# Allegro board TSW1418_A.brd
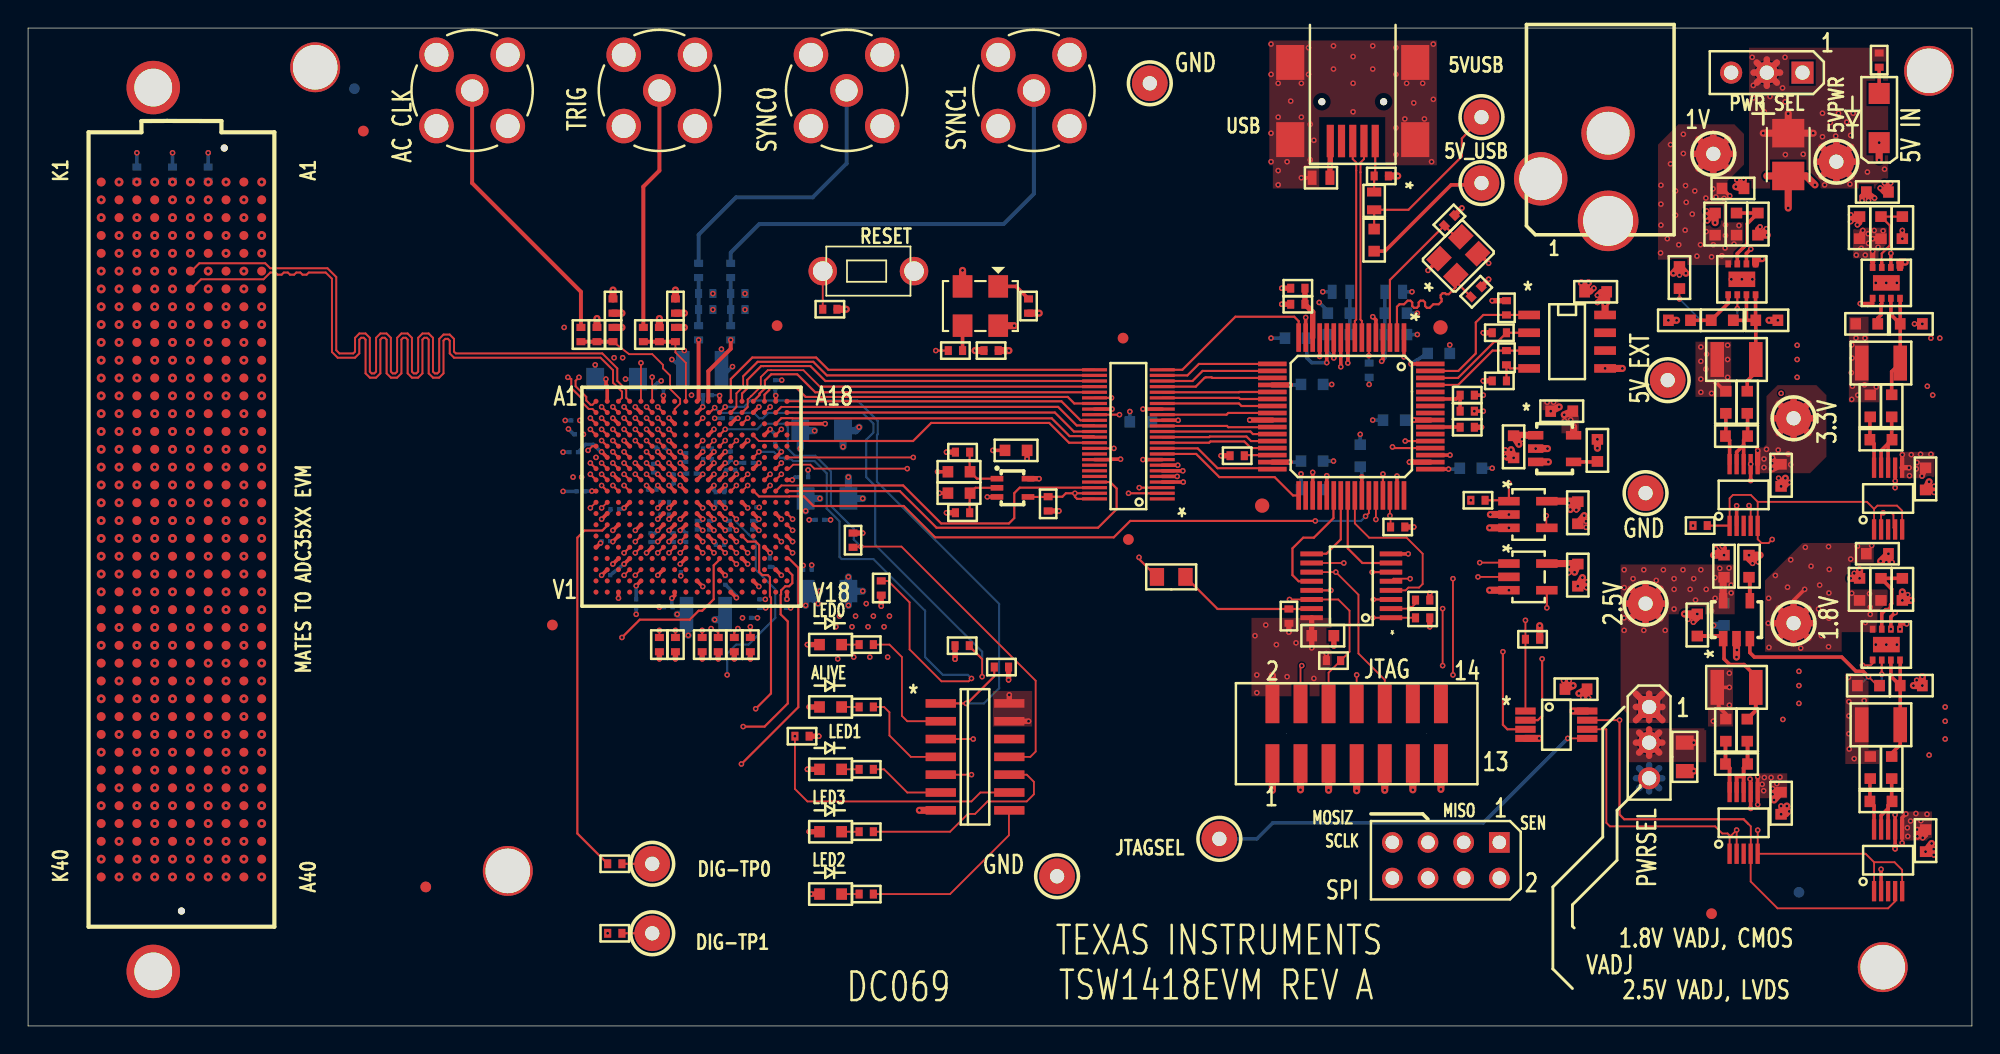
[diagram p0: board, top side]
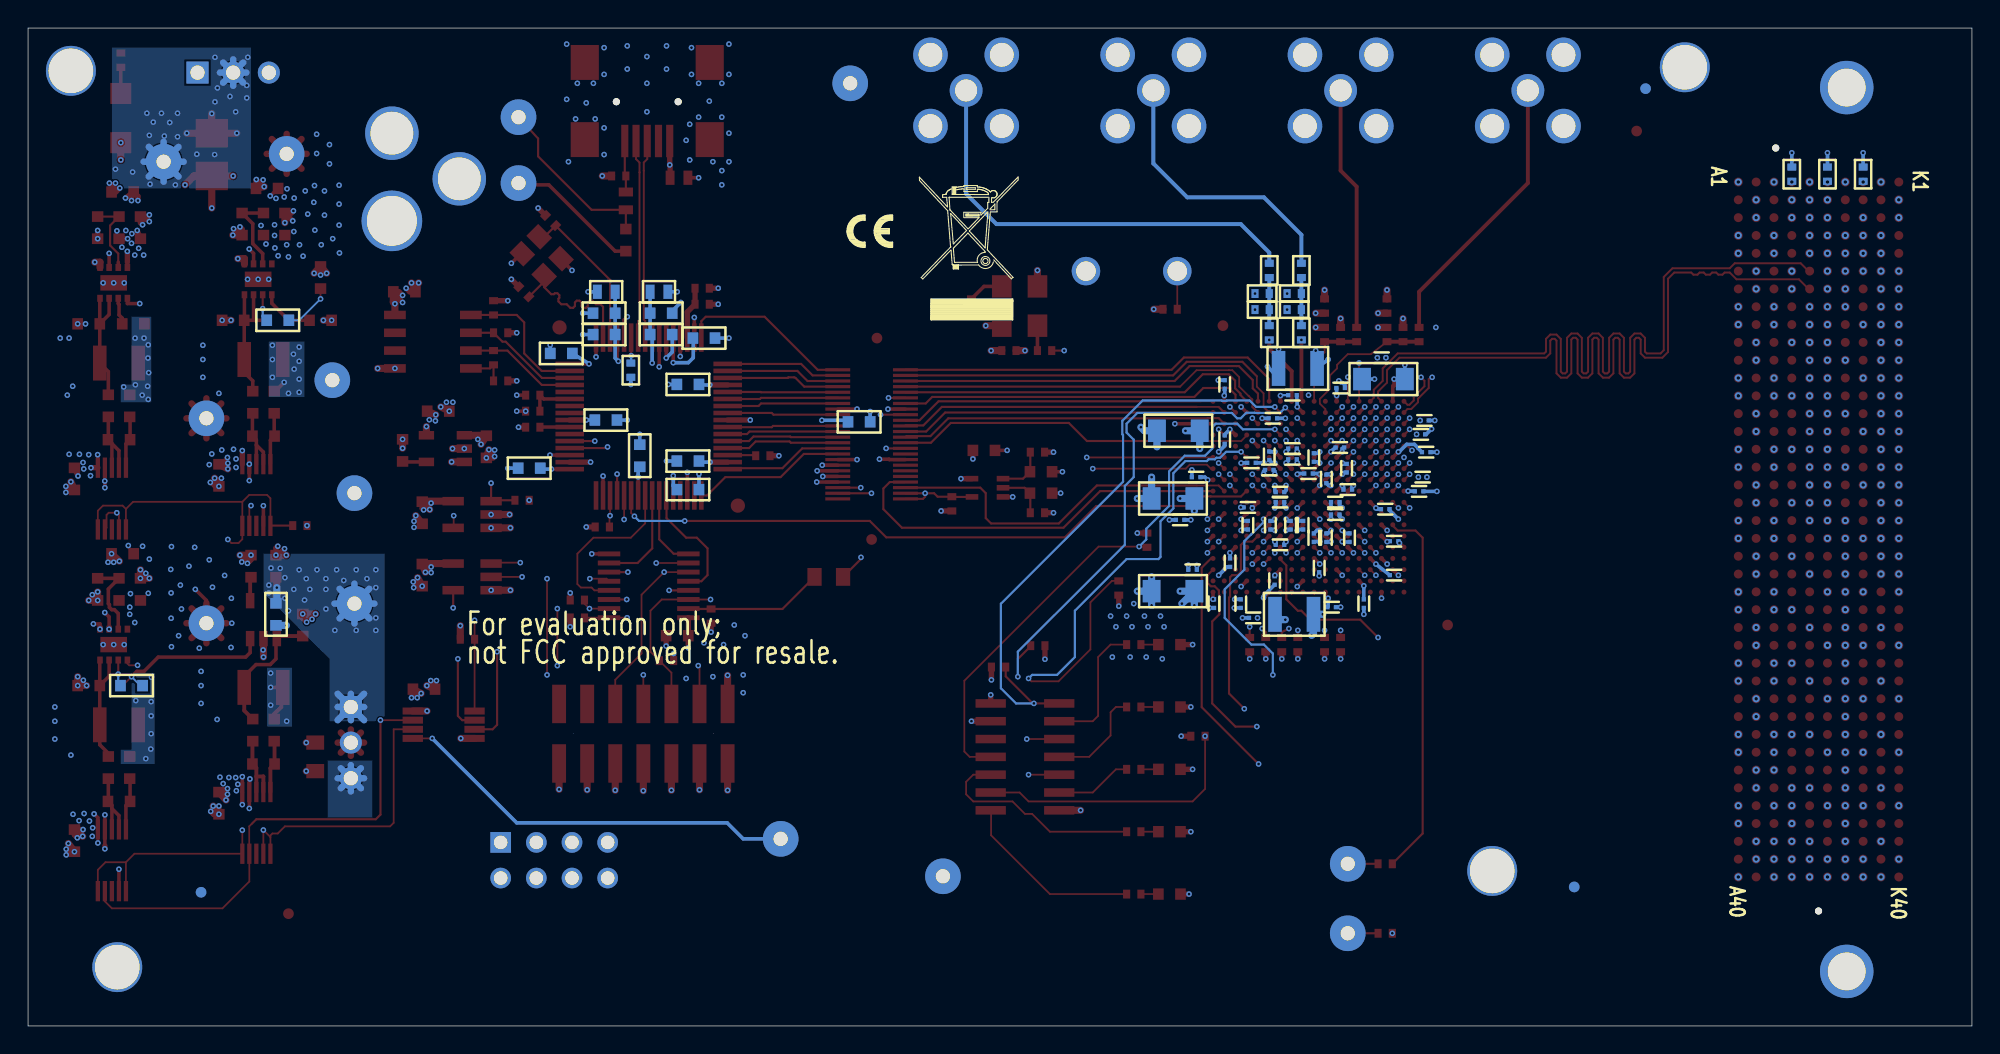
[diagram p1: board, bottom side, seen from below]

Outline 138.43 x 71.12 mm; copper layers: TOP, LY2-GND, LY3-SIGNAL, LY4-GND, LY5-SIGNAL, LY6-GND, LY7-PWR, LYR8-GND, LYR9-PWR, BOTTOM. Coordinates in mm from the lower left corner of the outline.
Outline path: 0,71.12 138.43,71.12 138.43,0 0,0 0,71.12

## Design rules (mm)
net group DCLK: nets DCLK_N DCLK_P
net group DCLKIN_FPGA: nets DCLKIN_FPGA_N DCLKIN_FPGA_P
net group DMP: nets DM DP
net group FCLK: nets FCLK_N FCLK_P
net group FPGA_CLK: nets FPGA_CLK_N FPGA_CLK_P
net group FPGA_REFCLK: nets FPGA_REFCLK_N FPGA_REFCLK_P
net group HA02: nets HA02_N HA02_P
net group HA03: nets HA03_N HA03_P
net group HA04: nets HA04_N HA04_P
net group HA05: nets HA05_N HA05_P
net group HA06: nets HA06_N HA06_P
net group HA07: nets HA07_N HA07_P
net group HA08: nets HA08_N HA08_P
net group HA09: nets HA09_N HA09_P
net group HA10: nets HA10_N HA10_P
net group HA11: nets HA11_N HA11_P
net group HA12: nets HA12_N HA12_P
net group HA13: nets HA13_N HA13_P
net group HA14: nets HA14_N HA14_P
net group HA15: nets HA15_N HA15_P
net group HA16: nets HA16_N HA16_P
net group HA18: nets HA18_N HA18_P
net group HA19: nets HA19_N HA19_P
net group HA20: nets HA20_N HA20_P
net group HA21: nets HA21_N HA21_P
net group HA22: nets HA22_N HA22_P
net group HA23: nets HA23_N HA23_P

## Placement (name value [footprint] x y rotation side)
C1  0.1uF  [0603]  93.34 50.8 180 bottom
C2  4.7uF  [0603]  93.34 49.28 180 bottom
C3  2.2uF  [0603]  109.22 43.81 180 top
C4  3.3uF  [0603]  90.3 49.02 180 bottom
C5  0.1uF  [0603]  91.44 38.23 180 bottom
C6  0.1uF  [0603]  100.46 47.93 0 bottom
C7  0.1uF  [0603]  102.74 39.75 0 bottom
C8  0.1uF  [0603]  94.87 40.64 90 bottom
C9  0.1uF  [0603]  91.44 40.26 0 bottom
C10  0.1uF  [0603]  97.28 43.18 180 bottom
C11  0.1uF  [0603]  91.44 45.72 0 bottom
C12  0.1uF  [0603]  97.41 49.28 0 bottom
C13  2.2uF  [0603]  105.79 41.27 270 top
C14  4.7uF  [0603]  97.41 50.8 0 bottom
C15  0.01uF  [0603]  111.76 41.02 90 top
C16  2.2uF  [0402]  96.37 60.58 0 top
C17  0.1uF  [0603]  79.25 43.05 180 bottom
C18  100pF  [0402]  90.42 51.44 180 top
C19  18pF  [0402]  103.12 52.32 45 top
C20  0.1uF  [0603]  111.63 52.32 180 top
C21  18pF  [0402]  101.22 57.4 45 top
C22  0.1uF  [0603]  66.29 39.5 180 top
C23  0.1uF  [0603]  66.29 37.97 180 top
C24  0.1uF  [0603]  70.36 41.02 180 top
C25  0.1uF  [0603]  92.2 27.81 0 top
C27  47uF  [1206]  56.9 37.59 0 bottom
C28  4.7uF  [0201]  47.24 39.37 180 bottom
C29  .47uF  [0201]  51.18 29.08 0 bottom
C31  4.7uF  [0201]  50.04 40.64 270 bottom
C32  .47uF  [0201]  56.39 36.07 0 bottom
C33  .47uF  [0201]  49.96 35.69 90 bottom
C34  .47uF  [0201]  50.04 39.62 0 bottom
C35  .47uF  [0201]  49.28 37.34 180 bottom
C36  .47uF  [0201]  45.97 34.8 270 bottom
C37  .47uF  [0201]  48.51 35.69 270 bottom
C38  100uF  [1210]  48.01 46.86 0 bottom
C39  .47uF  [0201]  48.39 44.96 0 bottom
C40  47uF  [1206]  41.91 46.1 180 bottom
C41  4.7uF  [0201]  39.12 39.12 180 bottom
C42  .47uF  [0201]  42.04 47.62 180 bottom
C43  .47uF  [0201]  52.07 30.1 270 bottom
C44  .47uF  [0201]  39.24 42.16 180 bottom
C45  .47uF  [0201]  43.31 30.1 270 bottom
C47  4.7uF  [0201]  38.86 40.89 180 bottom
C48  4.7uF  [0201]  38.99 43.15 180 bottom
C49  .47uF  [0201]  49.66 31.75 270 bottom
C50  .47uF  [0201]  41.15 34.54 180 bottom
C51  .47uF  [0201]  44.96 45.47 180 bottom
C52  .47uF  [0201]  39.37 38.1 180 bottom
C53  4.7uF  [0201]  45.59 29.84 180 bottom
C54  47uF  [1206]  56.9 30.99 0 bottom
C55  4.7uF  [0201]  53.98 30.1 270 bottom
C56  .47uF  [0201]  52.83 33.02 270 bottom
C57  .47uF  [0201]  51.56 35.69 270 bottom
C58  .47uF  [0201]  41.78 36.83 180 bottom
C59  .47uF  [0201]  55.5 32.51 0 bottom
C60  4.7uF  [0201]  41.15 32.13 0 bottom
C61  47uF  [1206]  56.52 42.42 0 bottom
C62  4.7uF  [0201]  49.78 43.31 180 bottom
C63  .47uF  [0201]  51.31 40.13 180 bottom
C64  .47uF  [0201]  53.21 41.78 270 bottom
C65  .47uF  [0201]  53.21 45.72 90 bottom
C66  .47uF  [0201]  55.24 39.12 0 bottom
C67  4.7uF  [0201]  51.56 36.96 0 bottom
C68  .47uF  [0201]  46.48 32.64 270 bottom
C69  100uF  [1210]  48.26 29.34 180 bottom
C70  4.7uF  [0201]  44.32 34.8 90 bottom
C71  4.7uF  [0201]  48.39 40.39 180 bottom
C72  4.7uF  [0201]  45.34 36.45 0 bottom
C73  4.7uF  [0201]  48.39 41.15 0 bottom
C74  4.7uF  [0201]  45.97 38.99 270 bottom
C75  4.7uF  [0201]  45.01 41.22 180 bottom
C76  .47uF  [0201]  47.62 35.69 90 bottom
C77  .47uF  [0201]  49.28 34.29 0 bottom
C78  .47uF  [0201]  44.45 38.23 180 bottom
C79  .47uF  [0201]  44.53 39.75 270 bottom
C80  .47uF  [0201]  49.28 38.05 0 bottom
C81  .47uF  [0201]  45.34 37.34 180 bottom
C82  .47uF  [0201]  46.86 34.8 90 bottom
C83  .47uF  [0201]  46.86 40.51 90 bottom
C84  .1uF  [0402]  68.58 48.13 180 top
C85  .1uF  [0402]  43.81 49.28 270 top
C86  .1uF  [0402]  46.1 51.31 270 top
C87  .1uF  [0402]  39.37 49.28 270 top
C88  .1uF  [0402]  41.66 51.31 270 top
C89  12pF  [0402]  50.55 51.05 0 bottom
C90  12pF  [0402]  48.26 51.05 0 bottom
C91  470uF  [TANT_B]  125.35 62.1 270 top
C92  0.1uF  [0603]  117.6 50.29 180 top
C94  10uF  [0603]  123.83 50.29 0 top
C95  22uF  [0603]  121.41 59.69 0 top
C96  0.1uF  [0603]  121.67 42.04 0 top
C98  0.1uF  [0603]  120.14 57.15 90 top
C99  0.1uF  [0603]  124.84 39.24 270 top
C101  10uF  [0603]  134.11 24.26 0 top
C102  22uF  [0603]  131.7 33.66 0 top
C103  0.1uF  [0603]  131.95 16 0 top
C104  0.1uF  [0603]  130.43 31.11 90 top
C105  0.1uF  [0603]  135.13 13.21 270 top
C107  10uF  [0603]  134.11 50.04 0 top
C108  22uF  [0603]  131.7 59.44 0 top
C109  0.1uF  [0603]  131.95 41.78 0 top
C110  0.1uF  [0603]  130.43 56.9 90 top
C111  0.1uF  [0603]  135.13 38.99 270 top
C118  0.1uF  [0603]  120.78 29.34 270 bottom
C119  0.1uF  [0603]  121.67 18.67 0 top
C120  0.1uF  [0603]  124.84 15.88 270 top
C121  0.1uF  [0603]  118.87 28.57 90 top
C122  0.1uF  [0603]  120.78 32.77 90 top
C123  0.01uF  [0603]  122.56 32.77 90 top
C124  0.1uF  [0603]  110.36 32.13 270 top
C125  0.1uF  [0603]  110.24 24 180 top
C126  0.1uF  [0603]  110.36 36.58 270 top
C127  1uF  [0805]  117.98 19.18 270 top
D2  LED GREEN  [LED_1206]  131.83 64.71 270 top
D3  LED BLUE  [LED_0603]  57.15 22.73 0 top
D4  LED BLUE  [LED_0603]  57.15 27.18 0 top
D5  LED BLUE  [LED_0603]  57.15 18.29 0 top
D6  LED BLUE  [LED_0603]  57.15 9.4 0 top
D7  LED BLUE  [LED_0603]  57.15 13.84 0 top
FB1  600 OHM  [IND_0603]  93.5 52.32 180 bottom
FB2  600 OHM  [IND_0603]  97.26 52.32 0 bottom
FB3  600 OHM  [IND_0603]  95.86 58.8 270 top
FB4  600 OHM  [IND_0603]  92.08 60.45 0 top
J2  CONN, USB, MINI  [CON_SMRT_USBMNE20_F]  94.34 66.52 270 top
J3  CON, SMVT, 2X7, 2MM, MALE  [HDR_SMVT_2X7_79_M]  94.61 20.83 0 top
J4  CONN JACK PWR  [CON_RAPC722_JACK_THVT_3]  112.52 60.5 180 top
J5  SMA, THVT, REC  [SMA_THVT_312X312]  44.96 66.67 0 top
J6  SMA, THVT, REC  [SMA_THVT_312X312]  31.62 66.67 0 top
J7  SMA, THVT, REC  [SMA_THVT_312X312]  71.63 66.67 0 top
J8  SMA, THVT, REC  [SMA_THVT_312X312]  58.29 66.67 0 top
J10  HDR, THVT, 3POS, .100  [HDR_THVT_1X3_100_M]  126.36 67.94 270 top
J11  HDR, THVT, 8POS, .100  [HDR_THVT_2X4_100_M]  104.78 13.08 270 top
J12  CON, SMVT, HS, FIELD ARRAY, FMC, FEMALE  [CON_SMVT_40X10_SEAF_MTG]  10.92 35.38 90 top
J13  HDR, THVT, 3POS, .100  [HDR_THVT_1X3_100_M]  115.44 22.73 0 top
MT1  STANDOFF, FEMALE, 4-40 X  1 3/16"  [MFG125_PLATED]  34.16 11.05 180 bottom
MT2  STANDOFF, FEMALE, 4-40 X  1 3/16"  [MFG125_PLATED]  20.45 68.33 180 bottom
MT3  STANDOFF, FEMALE, 4-40 X  1 3/16"  [MFG125_PLATED]  135.38 68.07 180 bottom
MT4  STANDOFF, FEMALE, 4-40 X  1 3/16"  [MFG125_PLATED]  132.08 4.19 180 bottom
NOREF  -  []  0 0 0 top
NOREF#2  -  []  127.13 -27.79 0 top
NOREF#3  -  [unnamed#2]  77.98 49.02 0 top
NOREF#4  -  [unnamed#2]  119.89 8 0 top
NOREF#5  -  []  -186.39 -215.8 0 top
NOREF#6  -  []  257.56 97.41 0 top
NOREF#7  -  []  0 0 90 top
NOREF#8  -  [unnamed#2]  78.36 34.67 0 top
NOREF#9  -  [unnamed#2]  53.34 49.91 0 top
NOREF#10  -  [unnamed#2]  37.34 28.57 0 top
NOREF#11  -  [unnamed#2]  28.32 9.91 0 top
NOREF#12  -  [unnamed#2]  23.88 63.78 180 top
NOREF#13  -  [unnamed#2]  28.32 9.91 180 bottom
NOREF#14  -  [unnamed#2]  23.24 66.8 0 bottom
NOREF#15  -  []  78.75 56.7 180 bottom
NOREF#16  -  []  107.31 27.94 180 bottom
NOREF#17  -  [unnamed#2]  126.11 9.53 180 bottom
NOREF#18  -  []  71.5 57.02 180 bottom
R1  4.7k  [0402]  86.11 40.64 0 top
R2  4.7k  [0402]  102.49 42.67 180 top
R3  .01  [0603]  95.86 56.01 270 top
R4  1k  [0402]  90.42 52.58 0 top
R5  12.1k  [0402]  95.5 46.74 90 bottom
R6  330  [0402]  59.69 27.18 0 top
R7  10K  [0402]  105.28 51.18 270 top
R8  10K  [0402]  104.78 49.4 0 top
R9  10K  [0402]  104.78 45.97 0 top
R10  2.2K  [0402]  105.28 47.62 270 top
R11  4.7k  [0402]  102.49 44.96 180 top
R12  2.2k  [0402]  66.55 40.89 0 top
R13  2.2k  [0402]  66.55 36.58 0 top
R14  10k  [0402]  102.49 43.81 0 top
R15  2.2k  [0402]  57.1 51.08 0 top
R18  10k  [0402]  99.31 29.08 0 top
R19  10k  [0402]  89.79 29.21 270 top
R20  2.2k  [0402]  48.01 27.18 90 top
R21  2.2k  [0402]  44.96 27.18 90 top
R22  470  [0402]  49.15 27.18 90 top
R23  470  [0402]  51.44 27.18 90 top
R24  470  [0402]  50.29 27.18 90 top
R25  2.2k  [0402]  46.1 27.18 90 top
R26  1k  [0402]  131.83 68.83 270 top
R27  10k  [0402]  72.64 37.21 90 top
R33  21  [0402]  41.78 11.56 0 top
R34  21  [0402]  41.78 6.6 0 top
R37  10k  [0402]  71.25 51.31 90 top
R38  49.9  [0402]  66.04 48.13 180 top
R39  100  [0402]  46.1 49.28 270 top
R40  100  [0402]  44.96 49.28 90 top
R41  100  [0402]  41.66 49.28 270 top
R42  100  [0402]  40.51 49.28 90 top
R43  18  [0402]  50.04 53.85 90 bottom
R44  18  [0402]  50.04 49.4 90 bottom
R45  18  [0402]  47.75 53.85 90 bottom
R46  18  [0402]  47.75 49.4 90 bottom
R49  10k  [0603]  120.65 50.29 180 top
R50  10k  [0603]  117.6 53.34 90 top
R51  24.9k  [0603]  121.67 57.15 90 top
R52  100k  [0603]  123.19 57.15 270 top
R53  10  [0603]  120.9 44.45 270 top
R54  10  [0603]  122.43 44.45 270 top
R56  10k  [0603]  131.06 24.26 180 top
R57  24.9k  [0603]  133.48 56.9 270 top
R58  100k  [0603]  133.48 31.11 270 top
R59  10  [0603]  131.19 18.41 270 top
R60  10  [0603]  132.72 18.41 270 top
R62  10k  [0603]  130.94 50.04 180 top
R63  76.8k  [0603]  131.95 56.9 90 top
R64  124k  [0603]  131.95 31.11 90 top
R65  10  [0603]  131.19 44.2 270 top
R66  10  [0603]  132.72 44.2 270 top
R71  10  [0603]  120.9 21.08 270 top
R72  10  [0603]  122.43 21.08 270 top
R73  .1  [1210]  131.95 47.24 0 top
R74  .1  [1210]  131.95 21.46 0 top
R75  .1  [1210]  121.67 24.13 0 top
R76  .1  [1210]  121.67 47.5 0 top
R77  0  [0603]  120.65 50.29 180 bottom
R78  0  [0603]  131.06 24.26 180 bottom
R79  10k  [0402]  92.96 26.04 0 top
R80  10k  [0402]  99.31 30.35 180 top
R81  330  [0402]  59.69 22.73 0 top
R82  330  [0402]  59.69 18.29 0 top
R83  330  [0402]  59.69 9.4 0 top
R84  330  [0402]  59.69 13.84 0 top
R85  2.2k  [0402]  97.54 35.56 0 top
R86  10k  [0402]  107.14 27.56 180 top
R87  10K  [0402]  66.52 27.1 0 top
R88  10K  [0402]  69.32 25.58 180 top
R89  10K  [0402]  60.76 31.21 90 top
R90  10K  [0402]  55.12 20.65 180 top
R91  10K  [0402]  58.75 34.62 270 top
R92  0  [0805]  81.41 32 0 top
R93  10k  [0402]  10.29 60.71 270 bottom
R94  10k  [0402]  12.83 60.71 270 bottom
R95  4.7k  [0402]  7.75 60.71 270 bottom
R96  2.2k  [0402]  103.25 37.47 0 top
R97  2.2k  [0402]  119.08 35.66 0 top
R98  18  [0402]  50.55 52.2 180 bottom
R99  18  [0402]  48.26 52.2 180 bottom
SW1  SW, PUSHBUTTON, SPST-NO  [SW_RESET_PTS635]  59.84 53.8 180 top
TP1  BLK  [TP_THVT_100_RND_GND]  79.88 67.18 0 top
TP2  BLK  [TP_THVT_100_RND_GND]  73.28 10.67 0 top
TP3  BLK  [TP_THVT_100_RND_GND]  115.19 37.97 90 top
TP4  RED  [TP_THVT_100_RND]  115.19 30.1 90 top
TP5  RED  [TP_THVT_100_RND]  125.73 28.7 90 top
TP6  RED  [TP_THVT_100_RND]  125.73 43.31 90 top
TP7  RED  [TP_THVT_100_RND]  103.5 64.77 0 top
TP8  RED  [TP_THVT_100_RND]  103.5 60.07 0 top
TP9  ORN  [TP_THVT_100_RND]  84.84 13.34 270 top
TP10  RED  [TP_THVT_100_RND]  116.76 46.02 90 top
TP11  ORN  [TP_THVT_100_RND]  44.45 11.56 0 top
TP12  ORN  [TP_THVT_100_RND]  44.45 6.6 0 top
TP15  RED  [TP_THVT_100_RND]  128.78 61.59 0 top
TP16  RED  [TP_THVT_100_RND]  120.02 62.15 90 top
U1  TPS73625  [SOT-23_5_63X114_DBV]  121.67 28.96 90 top
U2  TPS79933  [SOT-23_5_63X114_DBV]  108.71 41.15 0 top
U3  SN74CBTLV16210VR  [TVSOP_48_386X177_16]  78.36 42.16 180 top
U4  FT2232HL  [LQFP_64_402X402_20]  94.23 43.43 270 top
U5  93LC46BT-I/SN  [SO_8_193X154_50]  109.6 48.77 0 top
U6  74LVC1G38  [SC70_DCK_G5]  70.1 38.35 0 top
U7  74CBTLV3257  [TSSOP_16_201X177_26]  94.23 31.37 180 top
U8  SN74LVC1G125  [SOT_5_120X69_57]  106.81 36.45 270 top
U9  XC7A100T-1CSG324C  [BGA_324_15MMX15MM_0P8MM]  47.24 37.72 0 top
U10  SN74LVC1G125  [SOT_5_120X69_57]  106.81 32 270 top
U11  TPS82085  [USIL_8_3MMX2P8MM_0P65MM]  122.05 53.21 90 top
U12  INA226  [PSOP_10_122X122_0P5MM_DGS]  122.17 37.85 90 top
U13  TPS82085  [USIL_8_3MMX2P8MM_0P65MM]  132.33 27.18 90 top
U14  INA226  [PSOP_10_122X122_0P5MM_DGS]  132.46 11.81 90 top
U15  TPS82085  [USIL_8_3MMX2P8MM_0P65MM]  132.33 52.96 90 top
U16  INA226  [PSOP_10_122X122_0P5MM_DGS]  132.46 37.59 90 top
U17  INA226  [PSOP_10_122X122_0P5MM_DGS]  122.17 14.48 90 top
U18  SN74LVC07AD  [SOIC_14_344X157_50]  67.44 19.18 0 top
U20  PCA9536  [PSOP_8_118X118_26_DGK]  108.84 21.46 0 top
Y1  12MHz w/ 10pF  [XTAL_4_SM_130X102]  101.85 54.86 45 top
Y2  SM5545TEV-100.0MHZ  [OSC-3X5MM]  67.82 51.31 180 top

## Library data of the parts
C1 C5-C12 C17 C20 C22-C25 C96 C98 C99 C103-C105 C109-C111 C118-C122 C124-C126 = CAP0603: tolerance: 10%
C2 C14 = CAP NP_0: tolerance: 10%
C3 C13 = CAP_0603_2.2uF
C4 = CAP_0603_3.3uF
C15 C123 = CAP_0603_0.01uF
C16 = CAP_0402_2.2uF
C18 = CAP_0402_100pF
C19 C21 = CAP_0402_18pF
C27 C40 C54 C61 = CAP_1206_47uF
C28 C31 C41 C47 C48 C53 C55 C60 C62 C67 C70-C75 = CAP_0805_4.7uF_X7R_16V
C29 C32-C37 C39 C42-C45 C49-C52 C56-C59 C63-C66 C68 C76-C83 = CAP_0201_.47uF
C38 C69 = CAP_1206_100uF_6.3V
C84-C88 = CAP_0402_0.1uF
C89 C90 = CAP_0402_12pF
C91 = CAP_TANT_B_470uF_6.3V: tolerance: 20%
C92 = CAP_0603_0.1uF
C94 C101 C107 = CAP_0603_10uF
C95 C102 C108 = CAP_0603_22uF
C127 = CAP_0805_1uF_16V: tolerance: 10%, 16V, X7R
D2 = LED_GREEN_0
D3-D7 = LED
FB1-FB4 = FERRITE_BEAD_0603_330_H
J2 = USB_MINI_AB_MNE20-5G5P10
J3 = HEADER_2x7_100
J4 = CONN JACK PWR
J5-J8 = SMA-THVT_142-0701-201_REC_0
J10 J13 = HEADER_1x3_100
J11 = HEADER_2x4_100
J12 = CON_SMVT_40X10_SEAF
MT1-MT4 = MOUNTING_HOLE_1_3/16"
R1 R2 R11 R95 = Res_0402_4.7k
R3 = R: tolerance: 1%
R4 R26 = Res_0402_1k
R5 = Res_0402_12.1K
R6 R81-R84 = Res_0402_330
R7-R10 R87-R91 = RESISTOR
R12 R13 R15 R20 R21 R25 R85 R96 R97 = Res_0402_2.2K
R14 R18 R27 R79 R80 R86 R93 R94 = Res_0402_10k
R19 R37 = Res_0402_10k_H
R22-R24 = Res_0402_470
R33 R34 = Res_0402_21
R38 = Res_0402_49.9
R39-R42 = Res_0402_100
R43-R46 R98 R99 = Res_0402_18
R49 R50 R56 R62 = Res_0603_10k_H
R51 R57 R63 = Res_0603_24.9
R52 R58 R64 = Res_0603_100k
R53 R54 R59 R60 R65 R66 R71 R72 = Res_0402_1ohm
R73-R76 = Res_0603_.1
R77 R78 = Res_0603_Zero_H
R92 = Res_0805_Zero_H
SW1 = SW PUSHBUTTON
TP1-TP3 = TESTPOINT_BLK
TP4-TP8 TP10 TP15 TP16 = TESTPOINT_RED
TP9 TP11 TP12 = TESTPOINT_ORANGE
U1 = TPS73625
U2 = TPS79933
U3 = SN74CBTLV16210DGV
U4 = FT2232HL
U5 = EEPROM
U6 = 74LVC1G38
U7 = SN74CBTLV3257PWR
U8 U10 = SN74LVC1G125DBVR
U9 = XC7A100TCSG324
U11 U13 U15 = TPS82085
U12 U14 U16 U17 = INA226AIDGSR
U18 = SN74LVC07AD
U20 = PCA9536DGK
Y1 = CRYSTAL1-4/SM
Y2 = OSC

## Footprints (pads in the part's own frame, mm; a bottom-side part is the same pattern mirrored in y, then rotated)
0201
  rect 0.305x0.305 smd: 1(-0.305,0) 2(0.305,0)
0402
  rect 0.508x0.635 smd: 1(-0.508,0) 2(0.508,0)
0603
  rect 0.762x0.813 smd: 1(-0.787,0) 2(0.787,0)
0805
  rect 1.016x1.27 smd: 1(-1.016,0) 2(1.016,0)
1206
  rect 1.27x1.6 smd: 1(-1.524,0) 2(1.524,0)
1210
  rect 0.965x2.489 smd: 1(-1.372,0) 2(1.372,0)
BGA_324_15MMX15MM_0P8MM
  round 0.356 smd: A1(-6.8,6.8) A2(-6,6.8) A3(-5.2,6.8) A4(-4.4,6.8) A5(-3.6,6.8) A6(-2.8,6.8) A7(-2,6.8) A8(-1.2,6.8) A9(-0.4,6.8) A10(0.4,6.8) A11(1.2,6.8) A12(2,6.8) A13(2.8,6.8) A14(3.6,6.8) A15(4.4,6.8) A16(5.2,6.8) A17(6,6.8) A18(6.8,6.8) B1(-6.8,6) B2(-6,6) B3(-5.2,6) B4(-4.4,6) B5(-3.6,6) B6(-2.8,6) B7(-2,6) B8(-1.2,6) B9(-0.4,6) B10(0.4,6) B11(1.2,6) B12(2,6) B13(2.8,6) B14(3.6,6) B15(4.4,6) B16(5.2,6) B17(6,6) B18(6.8,6) C1(-6.8,5.2) C2(-6,5.2) C3(-5.2,5.2) C4(-4.4,5.2) C5(-3.6,5.2) C6(-2.8,5.2) C7(-2,5.2) C8(-1.2,5.2) C9(-0.4,5.2) C10(0.4,5.2) C11(1.2,5.2) C12(2,5.2) C13(2.8,5.2) C14(3.6,5.2) C15(4.4,5.2) C16(5.2,5.2) C17(6,5.2) C18(6.8,5.2) D1(-6.8,4.4) D2(-6,4.4) D3(-5.2,4.4) D4(-4.4,4.4) D5(-3.6,4.4) D6(-2.8,4.4) D7(-2,4.4) D8(-1.2,4.4) D9(-0.4,4.4) D10(0.4,4.4) D11(1.2,4.4) D12(2,4.4) D13(2.8,4.4) D14(3.6,4.4) D15(4.4,4.4) D16(5.2,4.4) D17(6,4.4) D18(6.8,4.4) E1(-6.8,3.6) E2(-6,3.6) E3(-5.2,3.6) E4(-4.4,3.6) E5(-3.6,3.6) E6(-2.8,3.6) E7(-2,3.6) E8(-1.2,3.6) E9(-0.4,3.6) E10(0.4,3.6) E11(1.2,3.6) E12(2,3.6) E13(2.8,3.6) E14(3.6,3.6) E15(4.4,3.6) E16(5.2,3.6) E17(6,3.6) E18(6.8,3.6) F1(-6.8,2.8) F2(-6,2.8) F3(-5.2,2.8) F4(-4.4,2.8) F5(-3.6,2.8) F6(-2.8,2.8) F7(-2,2.8) F8(-1.2,2.8) F9(-0.4,2.8) F10(0.4,2.8) F11(1.2,2.8) F12(2,2.8) F13(2.8,2.8) F14(3.6,2.8) F15(4.4,2.8) F16(5.2,2.8) F17(6,2.8) F18(6.8,2.8) G1(-6.8,2) G2(-6,2) G3(-5.2,2) G4(-4.4,2) G5(-3.6,2) G6(-2.8,2) G7(-2,2) G8(-1.2,2) G9(-0.4,2) G10(0.4,2) G11(1.2,2) G12(2,2) G13(2.8,2) G14(3.6,2) G15(4.4,2) G16(5.2,2) G17(6,2) G18(6.8,2) H1(-6.8,1.2) H2(-6,1.2) H3(-5.2,1.2) H4(-4.4,1.2) H5(-3.6,1.2) H6(-2.8,1.2) H7(-2,1.2) H8(-1.2,1.2) H9(-0.4,1.2) H10(0.4,1.2) H11(1.2,1.2) H12(2,1.2) H13(2.8,1.2) H14(3.6,1.2) H15(4.4,1.2) H16(5.2,1.2) H17(6,1.2) H18(6.8,1.2) J1(-6.8,0.4) J2(-6,0.4) J3(-5.2,0.4) J4(-4.4,0.4) J5(-3.6,0.4) J6(-2.8,0.4) J7(-2,0.4) J8(-1.2,0.4) J9(-0.4,0.4) J10(0.4,0.4) J11(1.2,0.4) J12(2,0.4) J13(2.8,0.4) J14(3.6,0.4) J15(4.4,0.4) J16(5.2,0.4) J17(6,0.4) J18(6.8,0.4) K1(-6.8,-0.4) K2(-6,-0.4) K3(-5.2,-0.4) K4(-4.4,-0.4) K5(-3.6,-0.4) K6(-2.8,-0.4) K7(-2,-0.4) K8(-1.2,-0.4) K9(-0.4,-0.4) K10(0.4,-0.4) K11(1.2,-0.4) K12(2,-0.4) K13(2.8,-0.4) K14(3.6,-0.4) K15(4.4,-0.4) K16(5.2,-0.4) K17(6,-0.4) K18(6.8,-0.4) L1(-6.8,-1.2) L2(-6,-1.2) L3(-5.2,-1.2) L4(-4.4,-1.2) L5(-3.6,-1.2) L6(-2.8,-1.2) L7(-2,-1.2) L8(-1.2,-1.2) L9(-0.4,-1.2) L10(0.4,-1.2) L11(1.2,-1.2) L12(2,-1.2) L13(2.8,-1.2) L14(3.6,-1.2) L15(4.4,-1.2) L16(5.2,-1.2) L17(6,-1.2) L18(6.8,-1.2) M1(-6.8,-2) M2(-6,-2) M3(-5.2,-2) M4(-4.4,-2) M5(-3.6,-2) M6(-2.8,-2) M7(-2,-2) M8(-1.2,-2) M9(-0.4,-2) M10(0.4,-2) M11(1.2,-2) M12(2,-2) M13(2.8,-2) M14(3.6,-2) M15(4.4,-2) M16(5.2,-2) M17(6,-2) M18(6.8,-2) N1(-6.8,-2.8) N2(-6,-2.8) N3(-5.2,-2.8) N4(-4.4,-2.8) N5(-3.6,-2.8) N6(-2.8,-2.8) N7(-2,-2.8) N8(-1.2,-2.8) N9(-0.4,-2.8) N10(0.4,-2.8) N11(1.2,-2.8) N12(2,-2.8) N13(2.8,-2.8) N14(3.6,-2.8) N15(4.4,-2.8) N16(5.2,-2.8) N17(6,-2.8) N18(6.8,-2.8) P1(-6.8,-3.6) P2(-6,-3.6) P3(-5.2,-3.6) P4(-4.4,-3.6) P5(-3.6,-3.6) P6(-2.8,-3.6) P7(-2,-3.6) P8(-1.2,-3.6) P9(-0.4,-3.6) P10(0.4,-3.6) P11(1.2,-3.6) P12(2,-3.6) P13(2.8,-3.6) P14(3.6,-3.6) P15(4.4,-3.6) P16(5.2,-3.6) P17(6,-3.6) P18(6.8,-3.6) R1(-6.8,-4.4) R2(-6,-4.4) R3(-5.2,-4.4) R4(-4.4,-4.4) R5(-3.6,-4.4) R6(-2.8,-4.4) R7(-2,-4.4) R8(-1.2,-4.4) R9(-0.4,-4.4) R10(0.4,-4.4) R11(1.2,-4.4) R12(2,-4.4) R13(2.8,-4.4) R14(3.6,-4.4) R15(4.4,-4.4) R16(5.2,-4.4) R17(6,-4.4) R18(6.8,-4.4) T1(-6.8,-5.2) T2(-6,-5.2) T3(-5.2,-5.2) T4(-4.4,-5.2) T5(-3.6,-5.2) T6(-2.8,-5.2) T7(-2,-5.2) T8(-1.2,-5.2) T9(-0.4,-5.2) T10(0.4,-5.2) T11(1.2,-5.2) T12(2,-5.2) T13(2.8,-5.2) T14(3.6,-5.2) T15(4.4,-5.2) T16(5.2,-5.2) T17(6,-5.2) T18(6.8,-5.2) U1(-6.8,-6) U2(-6,-6) U3(-5.2,-6) U4(-4.4,-6) U5(-3.6,-6) U6(-2.8,-6) U7(-2,-6) U8(-1.2,-6) U9(-0.4,-6) U10(0.4,-6) U11(1.2,-6) U12(2,-6) U13(2.8,-6) U14(3.6,-6) U15(4.4,-6) U16(5.2,-6) U17(6,-6) U18(6.8,-6) V1(-6.8,-6.8) V2(-6,-6.8) V3(-5.2,-6.8) V4(-4.4,-6.8) V5(-3.6,-6.8) V6(-2.8,-6.8) V7(-2,-6.8) V8(-1.2,-6.8) V9(-0.4,-6.8) V10(0.4,-6.8) V11(1.2,-6.8) V12(2,-6.8) V13(2.8,-6.8) V14(3.6,-6.8) V15(4.4,-6.8) V16(5.2,-6.8) V17(6,-6.8) V18(6.8,-6.8)
CON_RAPC722_JACK_THVT_3
  round 4.318 hole 3.556: 1(0,3.124)
  round 3.81 hole 3.048: 2(0,-3.124) 3(4.801,0.127)
CON_SMRT_USBMNE20_F
  round 0.508 hole 0.991 unplated: (0.65,2.2) (0.65,-2.2)
  rect 2.311x0.508 smd: 1(3.45,1.6) 2(3.45,0.8) 3(3.45,0) 4(3.45,-0.8) 5(3.45,-1.6)
  rect 2.489x2.007 smd: 6(-2.15,-4.45) 7(3.35,-4.45) 8(3.35,4.45) 9(-2.15,4.45)
CON_SMVT_40X10_SEAF_MTG
  round 3.81 hole 2.692: (-31.496,2.007) (31.496,2.007)
  round 0.508 hole 1.27 unplated: (-27.191,0) (27.189,-3.05)
  round 0.635 smd: A1(24.765,-5.715) A2(23.495,-5.715) A3(22.225,-5.715) A4(20.955,-5.715) A5(19.685,-5.715) A6(18.415,-5.715) A7(17.145,-5.715) A8(15.875,-5.715) A9(14.605,-5.715) A10(13.335,-5.715) A11(12.065,-5.715) A12(10.795,-5.715) A13(9.525,-5.715) A14(8.255,-5.715) A15(6.985,-5.715) A16(5.715,-5.715) A17(4.445,-5.715) A18(3.175,-5.715) A19(1.905,-5.715) A20(0.635,-5.715) A21(-0.635,-5.715) A22(-1.905,-5.715) A23(-3.175,-5.715) A24(-4.445,-5.715) A25(-5.715,-5.715) A26(-6.985,-5.715) A27(-8.255,-5.715) A28(-9.525,-5.715) A29(-10.795,-5.715) A30(-12.065,-5.715) A31(-13.335,-5.715) A32(-14.605,-5.715) A33(-15.875,-5.715) A34(-17.145,-5.715) A35(-18.415,-5.715) A36(-19.685,-5.715) A37(-20.955,-5.715) A38(-22.225,-5.715) A39(-23.495,-5.715) A40(-24.765,-5.715) B1(24.765,-4.445) B2(23.495,-4.445) B3(22.225,-4.445) B4(20.955,-4.445) B5(19.685,-4.445) B6(18.415,-4.445) B7(17.145,-4.445) B8(15.875,-4.445) B9(14.605,-4.445) B10(13.335,-4.445) B11(12.065,-4.445) B12(10.795,-4.445) B13(9.525,-4.445) B14(8.255,-4.445) B15(6.985,-4.445) B16(5.715,-4.445) B17(4.445,-4.445) B18(3.175,-4.445) B19(1.905,-4.445) B20(0.635,-4.445) B21(-0.635,-4.445) B22(-1.905,-4.445) B23(-3.175,-4.445) B24(-4.445,-4.445) B25(-5.715,-4.445) B26(-6.985,-4.445) B27(-8.255,-4.445) B28(-9.525,-4.445) B29(-10.795,-4.445) B30(-12.065,-4.445) B31(-13.335,-4.445) B32(-14.605,-4.445) B33(-15.875,-4.445) B34(-17.145,-4.445) B35(-18.415,-4.445) B36(-19.685,-4.445) B37(-20.955,-4.445) B38(-22.225,-4.445) B39(-23.495,-4.445) B40(-24.765,-4.445) C1(24.765,-3.175) C2(23.495,-3.175) C3(22.225,-3.175) C4(20.955,-3.175) C5(19.685,-3.175) C6(18.415,-3.175) C7(17.145,-3.175) C8(15.875,-3.175) C9(14.605,-3.175) C10(13.335,-3.175) C11(12.065,-3.175) C12(10.795,-3.175) C13(9.525,-3.175) C14(8.255,-3.175) C15(6.985,-3.175) C16(5.715,-3.175) C17(4.445,-3.175) C18(3.175,-3.175) C19(1.905,-3.175) C20(0.635,-3.175) C21(-0.635,-3.175) C22(-1.905,-3.175) C23(-3.175,-3.175) C24(-4.445,-3.175) C25(-5.715,-3.175) C26(-6.985,-3.175) C27(-8.255,-3.175) C28(-9.525,-3.175) C29(-10.795,-3.175) C30(-12.065,-3.175) C31(-13.335,-3.175) C32(-14.605,-3.175) C33(-15.875,-3.175) C34(-17.145,-3.175) C35(-18.415,-3.175) C36(-19.685,-3.175) C37(-20.955,-3.175) C38(-22.225,-3.175) C39(-23.495,-3.175) C40(-24.765,-3.175) D1(24.765,-1.905) D2(23.495,-1.905) D3(22.225,-1.905) D4(20.955,-1.905) D5(19.685,-1.905) D6(18.415,-1.905) D7(17.145,-1.905) D8(15.875,-1.905) D9(14.605,-1.905) D10(13.335,-1.905) D11(12.065,-1.905) D12(10.795,-1.905) D13(9.525,-1.905) D14(8.255,-1.905) D15(6.985,-1.905) D16(5.715,-1.905) D17(4.445,-1.905) D18(3.175,-1.905) D19(1.905,-1.905) D20(0.635,-1.905) D21(-0.635,-1.905) D22(-1.905,-1.905) D23(-3.175,-1.905) D24(-4.445,-1.905) D25(-5.715,-1.905) D26(-6.985,-1.905) D27(-8.255,-1.905) D28(-9.525,-1.905) D29(-10.795,-1.905) D30(-12.065,-1.905) D31(-13.335,-1.905) D32(-14.605,-1.905) D33(-15.875,-1.905) D34(-17.145,-1.905) D35(-18.415,-1.905) D36(-19.685,-1.905) D37(-20.955,-1.905) D38(-22.225,-1.905) D39(-23.495,-1.905) D40(-24.765,-1.905) E1(24.765,-0.635) E2(23.495,-0.635) E3(22.225,-0.635) E4(20.955,-0.635) E5(19.685,-0.635) E6(18.415,-0.635) E7(17.145,-0.635) E8(15.875,-0.635) E9(14.605,-0.635) E10(13.335,-0.635) E11(12.065,-0.635) E12(10.795,-0.635) E13(9.525,-0.635) E14(8.255,-0.635) E15(6.985,-0.635) E16(5.715,-0.635) E17(4.445,-0.635) E18(3.175,-0.635) E19(1.905,-0.635) E20(0.635,-0.635) E21(-0.635,-0.635) E22(-1.905,-0.635) E23(-3.175,-0.635) E24(-4.445,-0.635) E25(-5.715,-0.635) E26(-6.985,-0.635) E27(-8.255,-0.635) E28(-9.525,-0.635) E29(-10.795,-0.635) E30(-12.065,-0.635) E31(-13.335,-0.635) E32(-14.605,-0.635) E33(-15.875,-0.635) E34(-17.145,-0.635) E35(-18.415,-0.635) E36(-19.685,-0.635) E37(-20.955,-0.635) E38(-22.225,-0.635) E39(-23.495,-0.635) E40(-24.765,-0.635) F1(24.765,0.635) F2(23.495,0.635) F3(22.225,0.635) F4(20.955,0.635) F5(19.685,0.635) F6(18.415,0.635) F7(17.145,0.635) F8(15.875,0.635) F9(14.605,0.635) F10(13.335,0.635) F11(12.065,0.635) F12(10.795,0.635) F13(9.525,0.635) F14(8.255,0.635) F15(6.985,0.635) F16(5.715,0.635) F17(4.445,0.635) F18(3.175,0.635) F19(1.905,0.635) F20(0.635,0.635) F21(-0.635,0.635) F22(-1.905,0.635) F23(-3.175,0.635) F24(-4.445,0.635) F25(-5.715,0.635) F26(-6.985,0.635) F27(-8.255,0.635) F28(-9.525,0.635) F29(-10.795,0.635) F30(-12.065,0.635) F31(-13.335,0.635) F32(-14.605,0.635) F33(-15.875,0.635) F34(-17.145,0.635) F35(-18.415,0.635) F36(-19.685,0.635) F37(-20.955,0.635) F38(-22.225,0.635) F39(-23.495,0.635) F40(-24.765,0.635) G1(24.765,1.905) G2(23.495,1.905) G3(22.225,1.905) G4(20.955,1.905) G5(19.685,1.905) G6(18.415,1.905) G7(17.145,1.905) G8(15.875,1.905) G9(14.605,1.905) G10(13.335,1.905) G11(12.065,1.905) G12(10.795,1.905) G13(9.525,1.905) G14(8.255,1.905) G15(6.985,1.905) G16(5.715,1.905) G17(4.445,1.905) G18(3.175,1.905) G19(1.905,1.905) G20(0.635,1.905) G21(-0.635,1.905) G22(-1.905,1.905) G23(-3.175,1.905) G24(-4.445,1.905) G25(-5.715,1.905) G26(-6.985,1.905) G27(-8.255,1.905) G28(-9.525,1.905) G29(-10.795,1.905) G30(-12.065,1.905) G31(-13.335,1.905) G32(-14.605,1.905) G33(-15.875,1.905) G34(-17.145,1.905) G35(-18.415,1.905) G36(-19.685,1.905) G37(-20.955,1.905) G38(-22.225,1.905) G39(-23.495,1.905) G40(-24.765,1.905) H1(24.765,3.175) H2(23.495,3.175) H3(22.225,3.175) H4(20.955,3.175) H5(19.685,3.175) H6(18.415,3.175) H7(17.145,3.175) H8(15.875,3.175) H9(14.605,3.175) H10(13.335,3.175) H11(12.065,3.175) H12(10.795,3.175) H13(9.525,3.175) H14(8.255,3.175) H15(6.985,3.175) H16(5.715,3.175) H17(4.445,3.175) H18(3.175,3.175) H19(1.905,3.175) H20(0.635,3.175) H21(-0.635,3.175) H22(-1.905,3.175) H23(-3.175,3.175) H24(-4.445,3.175) H25(-5.715,3.175) H26(-6.985,3.175) H27(-8.255,3.175) H28(-9.525,3.175) H29(-10.795,3.175) H30(-12.065,3.175) H31(-13.335,3.175) H32(-14.605,3.175) H33(-15.875,3.175) H34(-17.145,3.175) H35(-18.415,3.175) H36(-19.685,3.175) H37(-20.955,3.175) H38(-22.225,3.175) H39(-23.495,3.175) H40(-24.765,3.175) J1(24.765,4.445) J2(23.495,4.445) J3(22.225,4.445) J4(20.955,4.445) J5(19.685,4.445) J6(18.415,4.445) J7(17.145,4.445) J8(15.875,4.445) J9(14.605,4.445) J10(13.335,4.445) J11(12.065,4.445) J12(10.795,4.445) J13(9.525,4.445) J14(8.255,4.445) J15(6.985,4.445) J16(5.715,4.445) J17(4.445,4.445) J18(3.175,4.445) J19(1.905,4.445) J20(0.635,4.445) J21(-0.635,4.445) J22(-1.905,4.445) J23(-3.175,4.445) J24(-4.445,4.445) J25(-5.715,4.445) J26(-6.985,4.445) J27(-8.255,4.445) J28(-9.525,4.445) J29(-10.795,4.445) J30(-12.065,4.445) J31(-13.335,4.445) J32(-14.605,4.445) J33(-15.875,4.445) J34(-17.145,4.445) J35(-18.415,4.445) J36(-19.685,4.445) J37(-20.955,4.445) J38(-22.225,4.445) J39(-23.495,4.445) J40(-24.765,4.445) K1(24.765,5.715) K2(23.495,5.715) K3(22.225,5.715) K4(20.955,5.715) K5(19.685,5.715) K6(18.415,5.715) K7(17.145,5.715) K8(15.875,5.715) K9(14.605,5.715) K10(13.335,5.715) K11(12.065,5.715) K12(10.795,5.715) K13(9.525,5.715) K14(8.255,5.715) K15(6.985,5.715) K16(5.715,5.715) K17(4.445,5.715) K18(3.175,5.715) K19(1.905,5.715) K20(0.635,5.715) K21(-0.635,5.715) K22(-1.905,5.715) K23(-3.175,5.715) K24(-4.445,5.715) K25(-5.715,5.715) K26(-6.985,5.715) K27(-8.255,5.715) K28(-9.525,5.715) K29(-10.795,5.715) K30(-12.065,5.715) K31(-13.335,5.715) K32(-14.605,5.715) K33(-15.875,5.715) K34(-17.145,5.715) K35(-18.415,5.715) K36(-19.685,5.715) K37(-20.955,5.715) K38(-22.225,5.715) K39(-23.495,5.715) K40(-24.765,5.715)
HDR_SMVT_2X7_79_M
  round 0.025 hole 1.041 unplated: (-5,0.008) (5,0.008)
  rect 0.991x2.743 smd: 1(-6,-2.122) 2(-6,2.122) 3(-4,-2.122) 4(-4,2.122) 5(-2,-2.122) 6(-2,2.122) 7(0,-2.122) 8(0,2.122) 9(2,-2.122) 10(2,2.122) 11(4,-2.122) 12(4,2.122) 13(6,-2.122) 14(6,2.122)
HDR_THVT_1X3_100_M
  rect 1.575x1.575 hole 1.016: 1(0,0)
  round 1.575 hole 1.016: 2(0,-2.54) 3(0,-5.08)
HDR_THVT_2X4_100_M
  rect 1.473x1.473 hole 0.965: 1(0,0)
  round 1.473 hole 0.965: 2(2.54,0) 3(0,-2.54) 4(2.54,-2.54) 5(0,-5.08) 6(2.54,-5.08) 7(0,-7.62) 8(2.54,-7.62)
IND_0603
  rect 0.635x1.016 smd: 1(-0.635,0) 2(0.635,0)
LED_0603
  rect 0.762x0.813 smd: 1(-0.787,0) 2(0.787,0)
LED_1206
  rect 1.499x1.499 smd: 1(-1.753,0) 2(1.753,0)
LQFP_64_402X402_20
  round 1.016 smd: (-6.35,6.35) (6.35,-6.35)
  rect 2.032x0.33 smd: 1(-5.625,3.75) 2(-5.625,3.25) 3(-5.625,2.75) 4(-5.625,2.25) 5(-5.625,1.75) 6(-5.625,1.25) 7(-5.625,0.75) 8(-5.625,0.25) 9(-5.625,-0.25) 10(-5.625,-0.75) 11(-5.625,-1.25) 12(-5.625,-1.75) 13(-5.625,-2.25) 14(-5.625,-2.75) 15(-5.625,-3.25) 16(-5.625,-3.75) 33(5.625,-3.75) 34(5.625,-3.25) 35(5.625,-2.75) 36(5.625,-2.25) 37(5.625,-1.75) 38(5.625,-1.25) 39(5.625,-0.75) 40(5.625,-0.25) 41(5.625,0.25) 42(5.625,0.75) 43(5.625,1.25) 44(5.625,1.75) 45(5.625,2.25) 46(5.625,2.75) 47(5.625,3.25) 48(5.625,3.75)
  rect 0.33x2.032 smd: 17(-3.75,-5.625) 18(-3.25,-5.625) 19(-2.75,-5.625) 20(-2.25,-5.625) 21(-1.75,-5.625) 22(-1.25,-5.625) 23(-0.75,-5.625) 24(-0.25,-5.625) 25(0.25,-5.625) 26(0.75,-5.625) 27(1.25,-5.625) 28(1.75,-5.625) 29(2.25,-5.625) 30(2.75,-5.625) 31(3.25,-5.625) 32(3.75,-5.625) 49(3.75,5.625) 50(3.25,5.625) 51(2.75,5.625) 52(2.25,5.625) 53(1.75,5.625) 54(1.25,5.625) 55(0.75,5.625) 56(0.25,5.625) 57(-0.25,5.625) 58(-0.75,5.625) 59(-1.25,5.625) 60(-1.75,5.625) 61(-2.25,5.625) 62(-2.75,5.625) 63(-3.25,5.625) 64(-3.75,5.625)
MFG125_PLATED
  round 3.556 hole 3.175: 1(0,0)
OSC-3X5MM
  rect 1.4x1.6 smd: 1(-1.27,-1.4) 2(1.27,-1.4) 3(1.27,1.4) 4(-1.27,1.4)
PSOP_8_118X118_26_DGK
  rect 1.45x0.5 smd: 1(-2.205,0.98) 2(-2.205,0.33) 3(-2.205,-0.32) 4(-2.205,-0.97) 5(2.195,-0.97) 6(2.195,-0.32) 7(2.195,0.33) 8(2.195,0.98)
PSOP_10_122X122_0P5MM_DGS
  rect 1.448x0.305 smd: 1(-2.205,1) 2(-2.205,0.5) 3(-2.205,0) 4(-2.205,-0.5) 5(-2.205,-1) 6(2.195,-1) 7(2.195,-0.5) 8(2.195,0) 9(2.195,0.5) 10(2.195,1)
SC70_DCK_G5
  rect 0.9x0.4 smd: 1(-1.105,0.65) 2(-1.105,0) 3(-1.105,-0.65) 4(1.105,-0.65) 5(1.105,0.65)
SMA_THVT_312X312
  round 2.337 hole 1.575: 1(0,0)
  round 2.464 hole 1.702: 2(-2.54,2.54) 3(2.54,2.54) 4(2.54,-2.54) 5(-2.54,-2.54)
SO_8_193X154_50
  rect 1.549x0.61 smd: 1(-2.705,1.905) 2(-2.705,0.635) 3(-2.705,-0.635) 4(-2.705,-1.905) 5(2.705,-1.905) 6(2.705,-0.635) 7(2.705,0.635) 8(2.705,1.905)
SOIC_14_344X157_50
  rect 2.159x0.61 smd: 1(-2.44,3.81) 2(-2.44,2.54) 3(-2.44,1.27) 4(-2.44,0) 5(-2.44,-1.27) 6(-2.44,-2.54) 7(-2.44,-3.81) 8(2.44,-3.81) 9(2.44,-2.54) 10(2.44,-1.27) 11(2.44,0) 12(2.44,1.27) 13(2.44,2.54) 14(2.44,3.81)
SOT-23_5_63X114_DBV
  rect 1.092x0.61 smd: 1(-1.35,0.95) 2(-1.35,0) 3(-1.35,-0.95) 4(1.35,-0.95) 5(1.35,0.95)
SOT_5_120X69_57
  rect 0.61x1.524 smd: 1(-0.95,-1.35) 2(0,-1.35) 3(0.95,-1.35) 4(0.95,1.35) 5(-0.95,1.35)
SW_RESET_PTS635
  round 2.032 hole 1.397: 1(-3.251,0) 2(3.251,0)
TANT_B
  rect 2.032x2.286 smd: 1(-1.524,0) 2(1.524,0)
TP_THVT_100_RND
  round 2.54 hole 1.016: 1(0,0)
TP_THVT_100_RND_GND
  round 2.54 hole 1.016: 1(0,0)
TSSOP_16_201X177_26
  rect 1.6x0.35 smd: 1(-2.825,2.275) 2(-2.825,1.625) 3(-2.825,0.975) 4(-2.825,0.325) 5(-2.825,-0.325) 6(-2.825,-0.975) 7(-2.825,-1.625) 8(-2.825,-2.275) 9(2.825,-2.275) 10(2.825,-1.625) 11(2.825,-0.975) 12(2.825,-0.325) 13(2.825,0.325) 14(2.825,0.975) 15(2.825,1.625) 16(2.825,2.275)
TVSOP_48_386X177_16
  rect 1.778x0.229 smd: 1(-2.411,4.6) 2(-2.411,4.2) 3(-2.411,3.8) 4(-2.411,3.4) 5(-2.411,3) 6(-2.411,2.6) 7(-2.411,2.2) 8(-2.411,1.8) 9(-2.411,1.4) 10(-2.411,1) 11(-2.411,0.6) 12(-2.411,0.2) 13(-2.411,-0.2) 14(-2.411,-0.6) 15(-2.411,-1) 16(-2.411,-1.4) 17(-2.411,-1.8) 18(-2.411,-2.2) 19(-2.411,-2.6) 20(-2.411,-3) 21(-2.411,-3.4) 22(-2.411,-3.8) 23(-2.411,-4.2) 24(-2.411,-4.6) 25(2.411,-4.6) 26(2.411,-4.2) 27(2.411,-3.8) 28(2.411,-3.4) 29(2.411,-3) 30(2.411,-2.6) 31(2.411,-2.2) 32(2.411,-1.8) 33(2.411,-1.4) 34(2.411,-1) 35(2.411,-0.6) 36(2.411,-0.2) 37(2.411,0.2) 38(2.411,0.6) 39(2.411,1) 40(2.411,1.4) 41(2.411,1.8) 42(2.411,2.2) 43(2.411,2.6) 44(2.411,3) 45(2.411,3.4) 46(2.411,3.8) 47(2.411,4.2) 48(2.411,4.6)
unnamed#2
  round 0.762 smd: (0,0)
USIL_8_3MMX2P8MM_0P65MM
  rect 0.5x0.4 smd: 1(-1.1,0.975) 2(-1.1,0.325) 3(-1.1,-0.325) 4(-1.1,-0.975) 5(1.1,-0.975) 6(1.1,-0.325) 7(1.1,0.325) 8(1.1,0.975)
  rect 1.1x1.9 smd: 9(0,0)
XTAL_4_SM_130X102
  rect 1.4x1.2 smd: 1(-1.1,-0.85) 2(1.1,-0.85) 3(1.1,0.85) 4(-1.1,0.85)

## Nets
1.8V: C27.1 C28.1 C29.1 C31.1 C32.1 C33.1 C34.1 C35.1 C102.1 C104.1 J13.3 R64.1 TP5.1(TP) U9.F12(VCCAUX#F12) U9.H10(VCCADC_0) U9.H12(VCCAUX#H12) U9.K12(VCCAUX#K12) U9.M12(VCCAUX#M12) U13.8(VOUT)
1.8V_USB: C4.1 C5.1 C6.1 C7.1 U4.12(VCORE#12) U4.37(VCORE#37) U4.49(VREGOUT) U4.64(VCORE#64)
1V: C36.1 C37.1 C38.1 C69.1 C70.1 C71.1 C72.1 C73.1 C74.1 C75.1 C76.1 C77.1 C78.1 C79.1 C80.1 C81.1 C82.1 C83.1 C95.1 C98.1 R51.1 TP16.1(TP) U9.F8(VCCINT#F8) U9.F10(VCCBRAM#F10) U9.G7(VCCINT#G7) U9.G9(VCCINT#G9) U9.G11(VCCBRAM#G11) U9.H8(VCCINT#H8) U9.J7(VCCINT#J7) U9.J11(VCCINT#J11) U9.K8(VCCINT#K8) U9.L7(VCCINT#L7) U9.L11(VCCINT#L11) U9.M8(VCCINT#M8) U9.M10(VCCINT#M10) U9.N7(VCCINT#N7) U9.N9(VCCINT#N9) U9.N11(VCCINT#N11) U11.8(VOUT)
2.5V: C118.1 C122.1 J13.1 TP4.1(TP) U1.5(OUT)
3.3V: C17.1 C25.1 C39.1 C61.1 C62.1 C63.1 C64.1 C65.1 C66.1 C67.1 C68.1 C84.1 C86.2 C88.2 C99.1 C105.1 C108.1 C110.1 C111.1 C120.1 C124.1 C125.1 C126.1 D3.1(ANODE) D4.1(ANODE) D5.1(ANODE) D6.1(ANODE) D7.1(ANODE) J3.2 J12.C39 J12.D32 J12.D36 J12.D38 J12.D40 R12.1 R15.2 R19.2 R20.1 R21.1 R22.1 R24.1 R25.1 R37.1 R39.1 R41.1 R63.1 R79.1 R80.1 R85.2 R86.1 R87.1 R88.1 R89.1 R90.1 R91.1 R93.1 R94.1 R95.1 TP6.1(TP) U3.15(VCC) U7.16(VCC) U8.5(VCC) U9.A17(VCCO_15#A17) U9.B10(VCCO_16) U9.C13(VCCO_15#C13) U9.D16(VCCO_15#D16) U9.G15(VCCO_15#G15) U9.H18(VCCO_15#H18) U9.K14(VCCO_15#K14) U9.R9(VCCO_0) U10.5(VCC) U12.6(VS) U14.2(A0) U14.6(VS) U15.8(VOUT) U16.6(VS) U17.6(VS) U18.13(6A) U18.14(VCC) U20.8(VCC) Y2.4(VCC)
3.3V_USB: C3.1 C8.1 C9.1 C10.1 C11.1 C20.1 C24.1 FB1.2 FB2.2 R1.1 R2.1 R4.1 R7.1 R8.1 R9.1 R13.1 R27.1 R96.1 R97.1 U2.5(OUT) U4.20(VCCIO#20) U4.31(VCCIO#31) U4.42(VCCIO#42) U4.50(VREGIN) U4.56(VCCIO#56) U5.8(VCC) U6.5(VCC)
5V_EXT: J4.1 J10.1 TP10.1(TP)
5V_PWR: C91.1 J10.2 R26.1 R50.2 R53.1 R56.2 R59.1 R62.2 R65.1 R71.1 R73.1 R74.1 R75.1 R76.1 TP15.1(TP)
5V_USB: C13.1 J10.3 R3.2 R11.1 TP8.1(TP) U2.1(IN) U2.3(EN)
GND: C1.2 C2.2 C3.2 C4.2 C5.2 C6.2 C7.2 C8.2 C9.2 C10.2 C11.2 C12.2 C13.2 C14.2 C15.2 C16.2 C17.2 C18.2 C19.2 C20.2 C21.2 C22.2 C23.2 C24.2 C25.2 C27.2 C28.2 C29.2 C31.2 C32.2 C33.2 C34.2 C35.2 C36.2 C37.2 C38.2 C39.2 C40.2 C41.2 C42.2 C43.2 C44.2 C45.2 C47.2 C48.2 C49.2 C50.2 C51.2 C52.2 C53.2 C54.2 C55.2 C56.2 C57.2 C58.2 C59.2 C60.2 C61.2 C62.2 C63.2 C64.2 C65.2 C66.2 C67.2 C68.2 C69.2 C70.2 C71.2 C72.2 C73.2 C74.2 C75.2 C76.2 C77.2 C78.2 C79.2 C80.2 C81.2 C82.2 C83.2 C84.2 C86.1 C88.1 C89.2 C90.2 C91.2 C92.2 C94.2 C95.2 C98.2 C99.2 C101.2 C102.2 C104.2 C105.2 C107.2 C108.2 C110.2 C111.2 C118.2 C120.2 C121.2 C122.2 C123.2 C124.2 C125.2 C126.2 C127.2 D2.2(CATHODE) FB4.2 J2.5(GND) J3.1 J3.3 J3.5 J3.7 J3.9 J3.11 J3.13 J4.2 J4.3 J5.2(GND#2) J5.3(GND#3) J5.4(GND#4) J5.5(GND#5) J6.2(GND#2) J6.3(GND#3) J6.4(GND#4) J6.5(GND#5) J7.2(GND#2) J7.3(GND#3) J7.4(GND#4) J7.5(GND#5) J8.2(GND#2) J8.3(GND#3) J8.4(GND#4) J8.5(GND#5) J11.2 J11.4 J11.6 J11.8 J12.A1 J12.A4 J12.A5 J12.A8 J12.A9 J12.A12 J12.A13 J12.A16 J12.A17 J12.A20 J12.A21 J12.A24 J12.A25 J12.A28 J12.A29 J12.A32 J12.A33 J12.A36 J12.A37 J12.A40 J12.B2 J12.B3 J12.B6 J12.B7 J12.B10 J12.B11 J12.B14 J12.B15 J12.B18 J12.B19 J12.B22 J12.B23 J12.B26 J12.B27 J12.B30 J12.B31 J12.B34 J12.B35 J12.B38 J12.B39 J12.C1 J12.C4 J12.C5 J12.C8 J12.C9 J12.C12 J12.C13 J12.C16 J12.C17 J12.C20 J12.C21 J12.C24 J12.C25 J12.C28 J12.C29 J12.C32 J12.C33 J12.C34 J12.C36 J12.C38 J12.C40 J12.D2 J12.D3 J12.D6 J12.D7 J12.D10 J12.D13 J12.D16 J12.D19 J12.D22 J12.D25 J12.D28 J12.D35 J12.D37 J12.D39 J12.E1 J12.E4 J12.E5 J12.E8 J12.E11 J12.E14 J12.E17 J12.E20 J12.E23 J12.E26 J12.E29 J12.E32 J12.E35 J12.E38 J12.E40 J12.F2 J12.F3 J12.F6 J12.F9 J12.F12 J12.F15 J12.F18 J12.F21 J12.F24 J12.F27 J12.F30 J12.F33 J12.F36 J12.F39 J12.G1 J12.G4 J12.G5 J12.G8 J12.G11 J12.G14 J12.G17 J12.G20 J12.G23 J12.G26 J12.G29 J12.G32 J12.G35 J12.G38 J12.G40 J12.H3 J12.H6 J12.H9 J12.H12 J12.H15 J12.H18 J12.H21 J12.H24 J12.H27 J12.H30 J12.H33 J12.H36 J12.H39 J12.J1 J12.J4 J12.J5 J12.J8 J12.J11 J12.J14 J12.J17 J12.J20 J12.J23 J12.J26 J12.J29 J12.J32 J12.J35 J12.J38 J12.J40 J12.K2 J12.K3 J12.K6 J12.K9 J12.K12 J12.K15 J12.K18 J12.K21 J12.K24 J12.K27 J12.K30 J12.K33 J12.K36 J12.K39 R5.1 R14.2 R18.2 R23.1 R40.2 R42.2 R52.2 R57.2 R58.2 SW1.1 TP1.1(TP) TP2.1(TP) TP3.1(TP) U1.2(GND) U2.2(GND) U3.4(1A3) U3.5(1A4) U3.6(1A5) U3.7(1A6) U3.8(GND1) U3.17(GND2) U3.32(GND3) U3.41(GND4) U4.1(GND#1) U4.5(GND#5) U4.10(AGND) U4.11(GND#11) U4.13(TEST) U4.15(GND#15) U4.25(GND#25) U4.35(GND#35) U4.47(GND#47) U4.51(GND#51) U5.5(GND) U6.3(GND) U7.8(GND) U8.2(A) U8.3(GND) U9.A2(GND#A2) U9.A12(GND#A12) U9.B5(GND#B5) U9.B15(GND#B15) U9.C8(GND#C8) U9.C18(GND#C18) U9.D1(GND#D1) U9.D11(GND#D11) U9.E4(GND#E4) U9.E8(VCCBATT_0) U9.E14(GND#E14) U9.F7(GND#F7) U9.F9(GND#F9) U9.F11(GND#F11) U9.F17(GND#F17) U9.G8(GND#G8) U9.G10(GND#G10) U9.G12(GND#G12) U9.H3(GND#H3) U9.H7(GND#H7) U9.H9(GNDADC) U9.H11(GND#H11) U9.H13(GND#H13) U9.J6(GND#J6) U9.J8(GND#J8) U9.J9(VREFN_0) U9.J12(GND#J12) U9.J16(GND#J16) U9.K7(GND#K7) U9.K10(VREFP_0) U9.K11(GND#K11) U9.L2(GND#L2) U9.L8(GND#L8) U9.L9(DXN_0) U9.L10(DXP_0) U9.L12(GND#L12) U9.M5(GND#M5) U9.M7(GND#M7) U9.M9(GND#M9) U9.M11(GND#M11) U9.M15(GND#M15) U9.N8(GND#N8) U9.N10(GND#N10) U9.N12(GND#N12) U9.N18(GND#N18) U9.P1(GND#P1) U9.R4(GND#R4) U9.R14(GND#R14) U9.T7(GND#T7) U9.T17(GND#T17) U9.U10(GND#U10) U9.V3(GND#V3) U9.V13(GND#V13) U10.3(GND) U11.5(GND#5) U11.6(GND#6) U11.9(PWRPAD) U12.2(A0) U12.7(GND) U13.5(GND#5) U13.6(GND#6) U13.9(PWRPAD) U14.7(GND) U15.5(GND#5) U15.6(GND#6) U15.9(PWRPAD) U16.7(GND) U17.7(GND) U18.7(GND) U20.4(GND) Y1.2 Y1.4 Y2.2(GND)
1P0V_SHUNTN: C94.1 R49.1 R54.1 R76.2 U11.3(VIN#3) U11.4(VIN#4)
1P8V_SHUNTN: C101.1 R60.1 R74.2 U13.3(VIN#3) U13.4(VIN#4)
2P5V_REG_EN: R56.1 R78.2 U1.3(EN) U15.1(EN)
2P5V_SHUNTN: C121.1 R72.1 R75.2 U1.1(IN)
3P3V_SHUNTN: C107.1 R66.1 R73.2 U15.3(VIN#3) U15.4(VIN#4)
AC-CLK-IN: C87.1 J6.1(CENTER)
AC_CLK: C87.2 R41.2 R42.1 U9.B8(IO_L12P_T1_MRCC)
ALIVE: R91.2 U9.D12(IO_L6P_T0) U18.11(5A)
BB_RDSTBN: U3.2(1A1) U4.53(BCBUS2)
BB_WRSTBN: U3.3(1A2) U4.52(BCBUS1)
BS_ENA: R27.2 R92.1 U3.47(2O\E\\) U3.48(1O\E\\) U6.4(Y)
D0_TCK_SCLK: U4.38(BDBUS0) U7.12(4A)
D1_TDI_MOSI: U4.39(BDBUS1) U7.9(3A)
D2_TDO_MISO: U4.40(BDBUS2) U7.7(2A)
D3_TMS_SEN: U4.41(BDBUS3) U7.4(1A)
DCLK_N: J12.F5 U9.D3(IO_L12N_T1_MRCC_35)
DCLK_P: J12.F4 U9.E3(IO_L12P_T1_MRCC_35)
DCLKIN_FPGA_N: J12.K17 U9.F3(IO_L13N_T2_MRCC_35)
DCLKIN_FPGA_P: J12.K16 U9.F4(IO_L13P_T2_MRCC_35)
DM: J2.2(D-) U4.7(DM)
DONE_0: R20.2 U9.P10(DONE_0) U20.3(P2)
DP: J2.3(D+) U4.8(DP)
EEDATA: R10.1 U4.61(EEDATA) U5.3(DI)
FCLK_N: J12.E3 U9.D4(IO_L11N_T1_SRCC_35)
FCLK_P: J12.E2 U9.D5(IO_L11P_T1_SRCC_35)
FIFO_CLKOUT: U3.10(1A8) U4.32(ACBUS5)
FIFO_D0: U3.24(2A10) U4.16(ADBUS0)
FIFO_D1: U3.23(2A9) U4.17(ADBUS1)
FIFO_D2: U3.22(2A8) U4.18(ADBUS2)
FIFO_D3: U3.21(2A7) U4.19(ADBUS3)
FIFO_D4: U3.20(2A6) U4.21(ADBUS4)
FIFO_D5: U3.19(2A5) U4.22(ADBUS5)
FIFO_D6: U3.18(2A4) U4.23(ADBUS6)
FIFO_D7: U3.16(2A3) U4.24(ADBUS7)
FIFO_OEN: U3.9(1A7) U4.33(ACBUS6)
FIFO_RDN: U3.12(1A10) U4.28(ACBUS2)
FIFO_RXFN: U3.14(2A2) U4.26(ACBUS0)
FIFO_TXEN: U3.13(2A1) U4.27(ACBUS1)
FIFO_WRN: U3.11(1A9) U4.29(ACBUS3)
FMC_GPIO_0: J12.G21 U9.L18(IO_L4P_T0_D04)
FMC_GPIO_1: J12.G22 U9.M18(IO_L4N_T0_D05)
FMC_GPIO_2: J12.G24 U9.R12(IO_L5P_T0_D06)
FMC_GPIO_3: J12.G25 U9.R13(IO_L5N_T0_D07)
FMC_MISO: J12.G30 U9.N14(IO_L8P_T1_D11)
FMC_MOSI: J12.G31 U9.T18(IO_L7N_T1_D10)
FMC_MOSI_EN: J12.G33 U9.R18(IO_L7P_T1_D09)
FMC_SCL: J12.G34 U9.P14(IO_L8N_T1_D12)
FMC_SCLK: J12.G27 U9.L13(IO_L6P_T0_FCS_B)
FMC_SDA_IN: J12.G37 U9.P18(IO_L9N_T1_DQS_D13)
FMC_SDA_OUT: J12.G36 U9.N17(IO_L9P_T1_DQS)
FMC_SEN: J12.G28 U9.M13(IO_L6N_T0_D08_VREF)
FPGA-TP0: R33.1 U9.M2(IO_L4N_T0_34)
FPGA-TP1: R34.1 U9.M3(IO_L4P_T0_34)
FPGA_CLK_N: J12.H5 U9.P5(IO_L13N_T2_MRCC_34)
FPGA_CLK_P: J12.H4 U9.N5(IO_L13P_T2_MRCC_34)
FPGA_REFCLK_N: J12.G7 U9.T4(IO_L12N_T1_MRCC_34)
FPGA_REFCLK_P: J12.G6 U9.T5(IO_L12P_T1_MRCC_34)
FTDI-BB-RDSTBN: U3.46(1B1) U9.J17(IO_L23P_T3_FOE_B)
FTDI-BB-WRSTBN: U3.45(1B2) U9.J18(IO_L23N_T3_FWE_B)
FTDI-FIFO-CLKOUT: U3.38(1B8) U9.D15(IO_L12P_T1_MRCC)
FTDI-FIFO-D0: U3.25(2B10) U9.A13(IO_L9P_T1_DQS_AD3P)
FTDI-FIFO-D1: U3.26(2B9) U9.B13(IO_L2P_T0_AD8P)
FTDI-FIFO-D2: U3.27(2B8) U9.A14(IO_L9N_T1_DQS_AD3N)
FTDI-FIFO-D3: U3.28(2B7) U9.B14(IO_L2N_T0_AD8N)
FTDI-FIFO-D4: U3.29(2B6) U9.A15(IO_L8P_T1_AD10P)
FTDI-FIFO-D5: U3.30(2B5) U9.C14(IO_L1N_T0_AD0N)
FTDI-FIFO-D6: U3.31(2B4) U9.A16(IO_L8N_T1_AD10N)
FTDI-FIFO-D7: U3.33(2B3) U9.B16(IO_L7P_T1_AD2P)
FTDI-FIFO-OEN: U3.39(1B7) U9.D17(IO_L16N_T2_A27)
FTDI-FIFO-RDN: U3.36(1B10) U9.B18(IO_L10P_T1_AD11P)
FTDI-FIFO-RXFN: U3.34(2B2) U9.A18(IO_L10N_T1_AD11N)
FTDI-FIFO-TXEN: U3.35(2B1) U9.B17(IO_L7N_T1_AD2N)
FTDI-FIFO-WRN: U3.37(1B9) U9.C17(IO_L20N_T3_A19)
HA02_N: J12.K8 U9.C7(IO_L4N_T0_35)
HA02_P: J12.K7 U9.D8(IO_L4P_T0_35)
HA03_N: J12.J7 U9.D7(IO_L6N_T0_VREF_35)
HA03_P: J12.J6 U9.E7(IO_L6P_T0_35)
HA04_N: J12.F8 U9.B1(IO_L9P_T1_DQS_AD7P_35)
HA04_P: J12.F7 U9.A1(IO_L9N_T1_DQS_AD7N_35)
HA05_N: J12.E7 U9.A3(IO_L8N_T1_AD14N_35)
HA05_P: J12.E6 U9.A4(IO_L8P_T1_AD14P_35)
HA06_N: J12.K11 U9.B6(IO_L2N_T0_AD12N_35)
HA06_P: J12.K10 U9.B7(IO_L2P_T0_AD12P_35)
HA07_N: J12.J10 U9.E1(IO_L18N_T2_35)
HA07_P: J12.J9 U9.F1(IO_L18P_T2_35)
HA08_N: J12.F11 U9.E6(IO_L5P_T0_AD13P_35)
HA08_P: J12.F10 U9.E5(IO_L5N_T0_AD13N_35)
HA09_N: J12.E10 U9.A5(IO_L3N_T0_DQS_AD5N_35)
HA09_P: J12.E9 U9.A6(IO_L3P_T0_DQS_AD5P_35)
HA10_N: J12.K14 U9.C1(IO_L16N_T2_35)
HA10_P: J12.K13 U9.C2(IO_L16P_T2_35)
HA11_N: J12.J13 U9.B4(IO_L7N_T1_AD6N_35)
HA11_P: J12.J12 U9.C4(IO_L7P_T1_AD6P_35)
HA12_N: J12.F14 U9.H1(IO_L17P_T2_35)
HA12_P: J12.F13 U9.G1(IO_L17N_T2_35)
HA13_N: J12.E13 U9.B2(IO_L10N_T1_AD15N_35)
HA13_P: J12.E12 U9.B3(IO_L10P_T1_AD15P_35)
HA14_N: J12.J16 U9.C6(IO_L1P_T0_AD4P_35)
HA14_P: J12.J15 U9.C5(IO_L1N_T0_AD4N_35)
HA15_N: J12.F17 U9.J3(IO_L22P_T3_35)
HA15_P: J12.F16 U9.J2(IO_L22N_T3_35)
HA16_N: J12.E16 U9.E2(IO_L14P_T2_SRCC_35)
HA16_P: J12.E15 U9.D2(IO_L14N_T2_SRCC_35)
HA18_N: J12.J19 U9.H6(IO_L24P_T3_35)
HA18_P: J12.J18 U9.H5(IO_L24N_T3_35)
HA19_N: J12.F20 U9.K2(IO_L23P_T3_35)
HA19_P: J12.F19 U9.K1(IO_L23N_T3_35)
HA20_N: J12.E19 U9.H4(IO_L21N_T3_DQS_35)
HA20_P: J12.E18 U9.J4(IO_L21P_T3_DQS_35)
HA21_N: J12.K20 U9.H2(IO_L15P_T2_DQS_35)
HA21_P: J12.K19 U9.G2(IO_L15N_T2_DQS_35)
HA22_N: J12.J22 U9.G4(IO_L20P_T3_35)
HA22_P: J12.J21 U9.G3(IO_L20N_T3_35)
HA23_N: J12.K23 U9.G6(IO_L19P_T3_35)
HA23_P: J12.K22 U9.F6(IO_L19N_T3_VREF_35)
INIT_B_0: R21.2 U9.P7(INIT_B_0) U20.2(P1)
JTAG_BS_EN: R19.1 R92.2 U7.15(O\E\)
JTAG_SEL: R18.1 TP9.1(TP) U7.1(S) U20.5(P3)
LED0: R88.2 U9.B12(IO_L3N_T0_DQS_AD1N) U18.1(1A)
LED1: R87.2 U9.B11(IO_L4P_T0) U18.3(2A)
LED2: R89.2 U9.F15(IO_L14P_T2_SRCC) U18.5(3A)
LED3: R90.2 U9.H14(IO_L15P_T2_DQS) U18.9(4A)
MISO: J11.3 U7.6(2B2) U9.J14(IO_L19P_T3_A22)
MOSI: U7.10(3B2) U9.G17(IO_L18N_T2_A23) U10.2(A)
MOSI_Z: J11.5 U10.4(Y)
OSC-OUT: R38.2 U9.H16(IO_L13P_T2_MRCC)
PROGRAM_B_0: R86.2 U9.P9(PROGRAM_B_0) U20.1(P0)
SCL: R97.2 U4.44(BDBUS5) U9.F18(IO_L22N_T3_A16) U12.1(A1) U12.5(SCL) U14.1(A1) U14.5(SCL) U16.1(A1) U16.5(SCL) U17.1(A1) U17.2(A0) U17.5(SCL) U20.6(SCL)
SCLK: J11.7 U7.13(4B2) U9.J13(IO_L17N_T2_A25)
SDA: R85.1 U4.46(BDBUS7) U8.4(Y) U9.G18(IO_L22P_T3_A17) U12.4(SDA) U14.4(SDA) U16.2(A0) U16.4(SDA) U17.4(SDA) U20.7(SDA)
SDA_OUT: R96.2 U4.45(BDBUS6) U8.1(O\E\)
SEN: J11.1 U7.3(1B2) U9.H17(IO_L18P_T2_A24)
SOUT0: C90.1 R45.1 R46.2 R99.2
SOUT1: C89.1 R43.1 R44.2 R98.2
SPI_D_Z: U4.43(BDBUS4) U9.J15(IO_L24N_T3_RS0) U10.1(O\E\)
SYNC0: R46.1 U9.A10(IO_L14P_T1_SRCC)
SYNC0_VADJ: R99.1 U9.R3(IO_L11P_T1_SRCC_34)
SYNC1: R44.1 U9.A11(IO_L4N_T0)
SYNC1_VADJ: R98.1 U9.P4(IO_L14P_T2_SRCC_34)
SYNC-OUT-0: J8.1(CENTER) R45.2
SYNC-OUT-1: J7.1(CENTER) R43.2
TCK: J3.6 R79.2 U7.14(4B1) U9.E10(TCK_0)
TDI: J3.10 U7.11(3B1) U9.E11(TDI_0)
TDO: J3.8 U7.5(2B1) U9.E13(TDO_0)
TMS: J3.4 R80.2 U7.2(1B1) U9.E12(TMS_0)
TRIG: C85.2 R39.2 R40.1 U9.A9(IO_L14N_T1_SRCC)
TRIG-IN: C85.1 J5.1(CENTER)
USB_EECLK: R8.2 U4.62(EECLK) U5.2(CLK)
USB_EECS: R7.2 U4.63(EECS) U5.1(CS)
USB_REF: R5.2 U4.6(REF)
USB_RST: C18.1 R4.2 U4.14(\\R\E\S\E\T\)
VADJ: C40.1 C41.1 C42.1 C43.1 C44.1 C45.1 C47.1 C48.1 C49.1 C50.1 C51.1 C52.1 C53.1 C54.1 C55.1 C56.1 C57.1 C58.1 C59.1 C60.1 C127.1 J12.E39 J12.F40 J12.G39 J12.H40 J13.2 U9.A7(VCCO_35#A7) U9.C3(VCCO_35#C3) U9.D6(VCCO_35#D6) U9.F2(VCCO_35#F2) U9.G5(VCCO_35#G5) U9.J1(VCCO_35#J1) U9.K4(VCCO_34#K4) U9.L15(IO_L3P_T0_DQS_PUDC_B) U9.L17(VCCO_14#L17) U9.N3(VCCO_34#N3) U9.N13(VCCO_14#N13) U9.P6(VCCO_34#P6) U9.P16(VCCO_14#P16) U9.T2(VCCO_34#T2) U9.T12(VCCO_14#T12) U9.U5(VCCO_34#U5) U9.U15(VCCO_14#U15) U9.V8(VCCO_34#V8) U9.V18(VCCO_14#V18)
N24747082: R9.2 R10.2 U5.4(DO)
N25673570: C1.1 C2.1 FB1.1 U4.9(VPLL)
N25674940: C12.1 C14.1 FB2.1 U4.4(VPHY)
N27319544: C19.1 U4.2(OSCI) Y1.1
N27322325: C21.1 U4.3(OSCO) Y1.3
N29832220: FB4.1 J2.6(GND1) J2.7(GND2) J2.8(GND3) J2.9(GND4)
N46253696: C16.1 FB3.1 J2.1(VBUS)
N46253708: FB3.2 R3.1 TP7.1(TP)
N46266315: C15.1 U2.4(NR/FB)
N46266800: R11.2 R14.1 U4.59(BCBUS7)
N46270507: R22.2 U9.P11(M2_0)
N46270525: R23.2 U9.P13(M1_0)
N46270552: R24.2 U9.P12(M0_0)
N46270638: R25.2 U9.P8(CFGBVS_0)
N46271778: R1.2 U4.30(ACBUS4)
N46271783: R2.2 U4.55(BCBUS4)
N46280543: C23.1 R13.2 U6.2(B)
N46280553: C22.1 R12.2 U6.1(A)
N46323629: R33.2 TP11.1(TP)
N46323688: R34.2 TP12.1(TP)
N46333997: C92.1 R49.2 U11.1(EN)
N46334199: R50.1 R77.2 U13.1(EN)
N46334233: R51.2 R52.1 U11.7(FB)
N46334693: C96.2 R54.2 U12.8(VBUS) U12.9(VIN-)
N46334712: C96.1 R53.2 U12.10(VIN+)
N46335690: R58.1 R64.2 U13.7(FB)
N46335801: C103.2 R60.2 U14.8(VBUS) U14.9(VIN-)
N46335828: C103.1 R59.2 U14.10(VIN+)
N46336358: R62.1 U15.2(PG)
N46336380: R57.1 R63.2 U15.7(FB)
N46336491: C109.2 R66.2 U16.8(VBUS) U16.9(VIN-)
N46336518: C109.1 R65.2 U16.10(VIN+)
N46342790: C119.2 R72.2 U17.8(VBUS) U17.9(VIN-)
N46342817: C119.1 R71.2 U17.10(VIN+)
N46365358: C123.1 U1.4(NR)
N46372732: R37.2 Y2.1(EN)
N46372902: R38.1 Y2.3(OUT)
N46384300: D3.2(CATHODE) R81.1
N46384467: D4.2(CATHODE) R6.1
N46384557: D5.2(CATHODE) R82.1
N46384754: D6.2(CATHODE) R83.1
N46384902: D7.2(CATHODE) R84.1
N46387156: D2.1(ANODE) R26.2
N46388372: R6.2 U18.2(1Y)
N46388377: R81.2 U18.4(2Y)
N46388382: R82.2 U18.6(3Y)
N46388387: R83.2 U18.8(4Y)
N46388402: R84.2 U18.10(5Y)
N46435188: R15.1 SW1.2 U9.C10(IO_L13N_T1_MRCC)
N46505112: J12.F1 R93.2
N46505156: J12.D1 R94.2
N46505187: J12.H1 R95.2
N463339328: R77.1 U11.2(PG)
N463356088: R78.1 U13.2(PG)

Pads without a net: J2 4; J3 12 14; J12 A2 A3 A6 A7 A10 A11 A14 A15 A18 A19 A22 A23 A26 A27 A30 A31 A34 A35 A38 A39 B1 B4 B5 B8 B9 B12 B13 B16 B17 B20 B21 B24 B25 B28 B29 B32 B33 B36 B37 B40 C2 C3 C6 C7 C10 C11 C14 C15 C18 C19 C22 C23 C26 C27 C30 C31 C35 C37 D4 D5 D8 D9 D11 D12 D14 D15 D17 D18 D20 D21 D23 D24 D26 D27 D29 D30 D31 D33 D34 E21 E22 E24 E25 E27 E28 E30 E31 E33 E34 E36 E37 F22 F23 F25 F26 F28 F29 F31 F32 F34 F35 F37 F38 G2 G3 G9 G10 G12 G13 G15 G16 G18 G19 H2 H7 H8 H10 H11 H13 H14 H16 H17 H19 H20 H22 H23 H25 H26 H28 H29 H31 H32 H34 H35 H37 H38 J2 J3 J24 J25 J27 J28 J30 J31 J33 J34 J36 J37 J39 K1 K4 K5 K25 K26 K28 K29 K31 K32 K34 K35 K37 K38 K40; MT1 1; MT2 1; MT3 1; MT4 1; U3 1 40 42 43 44; U4 34 36 48 54 57 58 60; U5 6 7; U9 A8 B9 C9 C11 C12 C15 C16 D9 D10 D13 D14 D18 E9 E15 E16 E17 E18 F5 F13 F14 F16 G13 G14 G16 H15 J5 J10 K3 K5 K6 K9 K13 K15 K16 K17 K18 L1 L3 L4 L5 L6 L14 L16 M1 M4 M6 M14 M16 M17 N1 N2 N4 N6 N15 N16 P2 P3 P15 P17 R1 R2 R5 R6 R7 R8 R10 R11 R15 R16 R17 T1 T3 T6 T8 T9 T10 T11 T13 T14 T15 T16 U1 U2 U3 U4 U6 U7 U8 U9 U11 U12 U13 U14 U16 U17 U18 V1 V2 V4 V5 V6 V7 V9 V10 V11 V12 V14 V15 V16 V17; U12 3; U14 3; U16 3; U17 3; U18 12

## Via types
v1: diameter 0.4, hole 0.203, TOP to BOTTOM, 876 vias
v2: diameter 0.508, hole 0.254, TOP to BOTTOM, 235 vias

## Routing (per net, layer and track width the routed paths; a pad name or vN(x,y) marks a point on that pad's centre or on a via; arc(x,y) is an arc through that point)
1.8V: length 47.5
  TOP w0.254: 125.73,30.12 125.73,30.33 v1(126.52,31.11) ; U9.H10 v1(48.04,39.32) ; U9.M12 v1(49.64,35.32) ; U9.F12 v1(49.64,40.92) ; U9.H12 v1(49.64,39.32) ; U9.K12 v1(49.64,36.92)
  TOP w0.457: TP5.1 126.79,29.76 ; TP5.1 127.15,28.7 ; TP5.1 126.79,27.65 ; TP5.1 125.73,30.12 ; TP5.1 124.31,28.7 ; TP5.1 124.67,27.65 ; TP5.1 124.67,29.76 ; TP5.1 125.73,27.28
  LY7-PWR w0.432: 124.31,28.7 TP5.1 ; TP5.1 127.15,28.7 ; TP5.1 124.67,29.76 ; TP5.1 125.73,30.12 ; TP5.1 126.79,27.65 ; TP5.1 126.79,29.76 ; TP5.1 124.67,27.65 ; TP5.1 125.73,27.28 ; J13.3 116.16,16.94 ; J13.3 116.16,18.37 ; J13.3 115.44,18.59 ; J13.3 114.5,17.65 ; J13.3 114.73,16.94 ; J13.3 115.44,16.71 ; J13.3 116.38,17.65 ; J13.3 114.73,18.37
  BOTTOM w0.254: C33.1 49.71,35.38 v1(49.64,35.32) ; v1(48.04,39.32) 47.99,39.37 C28.1 ; v1(49.64,36.92) 49.58,36.98 C35.1 ; C31.1 50.01,40.92 v1(49.64,40.92) ; C32.1 v1(55.63,36.07) ; C34.1 49.64,39.54 v1(49.64,39.32)
  BOTTOM w0.457: 114.73,18.37 J13.3 ; J13.3 114.73,16.94 ; J13.3 114.5,17.65 ; J13.3 116.16,18.37 ; J13.3 115.44,18.59 ; J13.3 116.16,16.94 ; J13.3 115.44,16.71 ; J13.3 116.38,17.65
  BOTTOM w0.508: v1(55.37,36.7) C27.1 v1(56.39,37.59)
  vias: v1(50.88,29.08) v1(123.93,28.7) v1(123.95,30.48) v1(123.98,26.97) v1(124.43,32.11) v1(125.3,31.27) v1(125.53,33.22) v1(126.24,26.92) v1(126.57,34.11) v1(126.97,32.77) v1(127.51,29.72) v1(127.58,31.42) v1(127.71,27.81) v1(128.22,34.16) v1(128.24,30.86) v1(128.24,29.06) v1(128.22,27.03) v1(128.27,32.54) v1(129.79,33.27) v1(129.87,30.84) v1(130.28,34.19) v1(130.84,28.75) v1(131.14,30.81) v1(131.19,29.84) v1(131.19,29.34) v1(131.29,34.24)
1.8V_USB: length 12.2
  TOP w0.254: U4.64 v1(98.48,47.18) ; U4.49 v1(101.16,39.68) ; U4.12 v1(92.48,47.27) ; U4.37 v1(92.48,39.22)
  BOTTOM w0.254: C5.1 92.48,38.48 v1(92.48,39.22) ; v1(92.48,47.27) 91.41,47.27 91.06,47.62 91.06,49 C4.1 ; v1(101.16,39.68) 101.89,39.68 C7.1 ; C6.1 98.48,47.2 v1(98.48,47.18)
